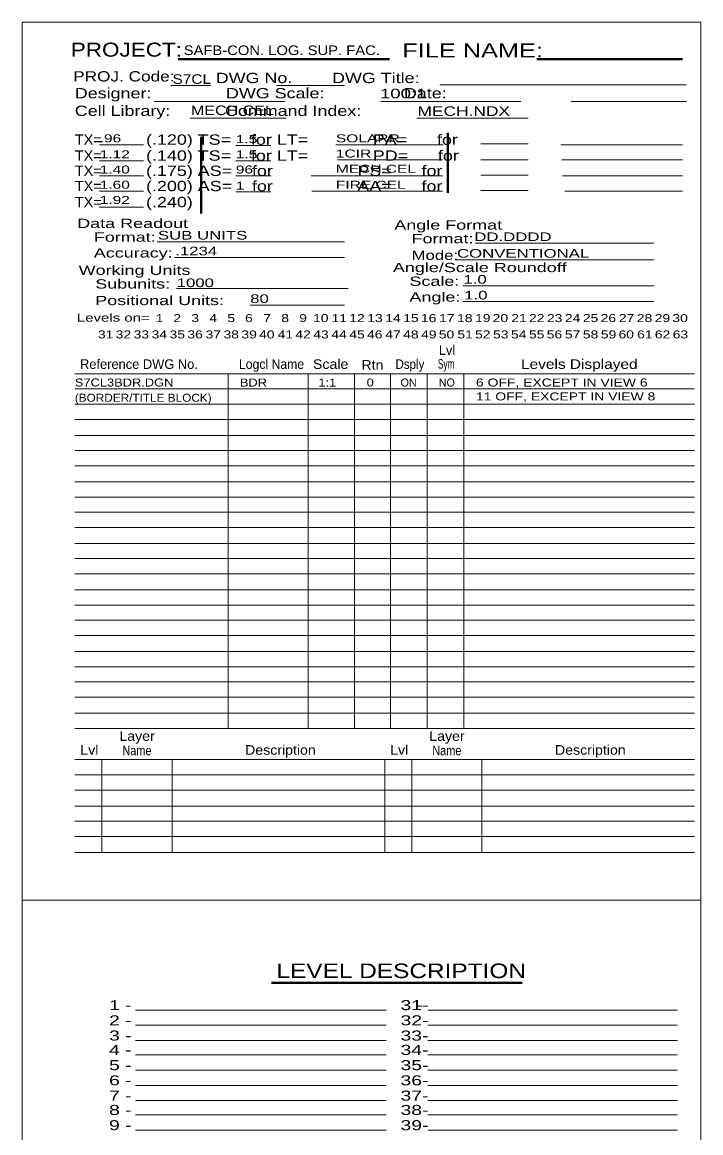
# Model space of a CAD drawing. Extents: x 55 to 190, y 198 to 264.
# Drawn here: x 168.12 to 189.71, y 221.76 to 257.1 of the extents above; entities that cross this region are included whole.
import ezdxf
from ezdxf.enums import TextEntityAlignment as Align

# ---------------------------------------------------------------- set-up
doc = ezdxf.new("R2010")
doc.units = 0
doc.header["$LTSCALE"] = 0.1
for name, color, linetype, lineweight in [('1', 7, 'Continuous', 25), ('2', 7, 'Continuous', 40), ('3', 7, 'Continuous', 25), ('5', 7, 'Continuous', 35), ('6', 7, 'Continuous', 25), ('8', 7, 'Continuous', 13)]:
    doc.layers.add(name, color=color, linetype=linetype, lineweight=lineweight)
for name, color, linetype in [('10', 7, 'Continuous'), ('11', 7, 'Continuous'), ('12', 7, 'Continuous'), ('13', 7, 'Continuous'), ('14', 7, 'Continuous'), ('15', 7, 'Continuous'), ('16', 7, 'Continuous'), ('17', 7, 'Continuous'), ('18', 7, 'Continuous'), ('19', 7, 'Continuous'), ('20', 7, 'Continuous'), ('21', 7, 'Continuous'), ('22', 7, 'Continuous'), ('23', 7, 'Continuous'), ('24', 7, 'Continuous'), ('25', 7, 'Continuous'), ('26', 7, 'Continuous'), ('27', 7, 'Continuous'), ('28', 7, 'Continuous'), ('29', 7, 'Continuous'), ('30', 7, 'Continuous'), ('31', 7, 'Continuous'), ('32', 7, 'Continuous'), ('33', 7, 'Continuous'), ('34', 7, 'Continuous'), ('35', 7, 'Continuous'), ('36', 7, 'Continuous'), ('37', 7, 'Continuous'), ('38', 7, 'Continuous'), ('39', 7, 'Continuous'), ('4', 7, 'Continuous'), ('40', 7, 'Continuous'), ('41', 7, 'Continuous'), ('42', 7, 'Continuous'), ('43', 7, 'Continuous'), ('44', 7, 'Continuous'), ('45', 7, 'Continuous'), ('46', 7, 'Continuous'), ('47', 7, 'Continuous'), ('48', 7, 'Continuous'), ('49', 7, 'Continuous'), ('50', 7, 'Continuous'), ('51', 7, 'Continuous'), ('52', 7, 'Continuous'), ('53', 7, 'Continuous'), ('54', 7, 'Continuous'), ('55', 7, 'Continuous'), ('56', 7, 'Continuous'), ('57', 7, 'Continuous'), ('58', 7, 'Continuous'), ('59', 7, 'Continuous'), ('60', 7, 'Continuous'), ('61', 7, 'Continuous'), ('62', 7, 'Continuous'), ('63', 7, 'Continuous'), ('7', 7, 'Continuous'), ('9', 7, 'Continuous')]:
    doc.layers.add(name, color=color, linetype=linetype)

msp = doc.modelspace()

# ---------------------------------------------------------------- linework, layer by layer
at = {"layer": '3', "lineweight": 13}
for points in [[(168.1177, 257.1025), (189.7077, 257.1025), (189.7077, 229.1625), (168.1177, 229.1625)], [(168.1177, 229.1625), (189.7077, 229.1625), (189.7077, 201.2225), (168.1177, 201.2225)]]:
    msp.add_lwpolyline(points, close=True, dxfattribs=at)
at = {"layer": '8', "lineweight": 40}
for p, q in [((179.804, 255.93), (173.0777, 255.93)), ((189.1277, 255.93), (184.4915, 255.93)), ((173.8165, 253.4587), (173.8165, 251.0137)), ((181.664, 251.675), (181.664, 253.5862)), ((176.0515, 226.5325), (184.0252, 226.5325))]:
    msp.add_line(p, q, dxfattribs=at)
at = {"layer": '8'}
for p, q in [((174.1227, 255.09), (172.8477, 255.09)), ((178.3765, 255.09), (176.2115, 255.09)), ((189.2565, 255.115), (181.409, 255.115)), ((172.3127, 254.5787), (176.4652, 254.5787)), ((179.5227, 254.5787), (183.9815, 254.5787)), ((185.5865, 254.5787), (189.2565, 254.5787)), ((173.4602, 254.045), (176.5177, 254.045)), ((180.6702, 254.045), (184.2115, 254.045)), ((171.9815, 253.2037), (170.5815, 253.2037)), ((176.0327, 253.1787), (174.9127, 253.1787)), ((181.5102, 253.2037), (178.0977, 253.2037)), ((184.2115, 253.2287), (182.7077, 253.2287)), ((189.1277, 253.2037), (185.2565, 253.2037)), ((171.9815, 252.695), (170.5815, 252.695)), ((176.0327, 252.695), (174.9127, 252.695)), ((181.4852, 252.72), (178.1477, 252.72)), ((184.2115, 252.72), (182.7077, 252.72)), ((189.1277, 252.72), (185.2815, 252.72)), ((171.9815, 252.2112), (170.5815, 252.2112)), ((176.0327, 252.2112), (174.9127, 252.2112)), ((181.4852, 252.2112), (177.3077, 252.2112)), ((184.2115, 252.2362), (182.7077, 252.2362)), ((189.1277, 252.2112), (185.3065, 252.2112)), ((171.9815, 251.7262), (170.5815, 251.7262)), ((176.0327, 251.7), (174.9127, 251.7)), ((181.4852, 251.7262), (177.3327, 251.7262)), ((184.2115, 251.7512), (182.7077, 251.7512)), ((189.1277, 251.7262), (185.3827, 251.7262)), ((171.9815, 251.2162), (170.5815, 251.2162)), ((178.3752, 250.1175), (172.4115, 250.1175)), ((182.524, 250.0687), (188.2115, 250.0687)), ((178.3752, 249.615), (172.9627, 249.615)), ((188.2115, 249.54), (181.9065, 249.54)), ((178.4902, 248.6275), (173.0315, 248.6275)), ((188.2115, 248.7137), (182.134, 248.7137)), ((178.3752, 248.1), (175.3715, 248.1)), ((188.2115, 248.2112), (182.134, 248.2112)), ((189.5102, 245.9175), (169.7915, 245.9175)), ((174.6752, 245.9175), (174.6752, 234.63)), ((177.219, 245.9175), (177.219, 234.63)), ((178.6865, 245.9175), (178.6865, 234.63)), ((179.834, 245.9175), (179.834, 234.6562)), ((181.004, 245.9175), (181.004, 234.63)), ((182.1727, 245.9175), (182.1727, 234.6562)), ((189.5102, 245.4325), (169.7915, 245.4325)), ((189.5102, 244.9487), (169.7915, 244.9487)), ((189.5102, 244.465), (169.7915, 244.465)), ((189.5102, 243.9562), (169.7915, 243.9562)), ((189.5102, 243.4725), (169.7915, 243.4725)), ((189.5102, 242.9875), (169.7915, 242.9875)), ((189.5102, 242.4775), (169.7915, 242.4775)), ((189.5102, 241.9937), (169.7915, 241.9937)), ((189.5102, 241.5087), (169.7915, 241.5087)), ((189.5102, 241.025), (169.7915, 241.025)), ((189.5102, 240.5162), (169.7915, 240.5162)), ((189.5102, 240.0325), (169.7915, 240.0325)), ((189.5102, 239.5487), (169.7915, 239.5487)), ((189.5102, 239.0375), (169.7915, 239.0375)), ((189.5102, 238.5537), (169.7915, 238.5537)), ((189.5102, 238.07), (169.7915, 238.07)), ((189.5102, 237.5862), (169.7915, 237.5862)), ((189.5102, 237.0762), (169.7915, 237.0762)), ((189.5102, 236.5925), (169.7915, 236.5925)), ((189.5102, 236.1087), (169.7915, 236.1087)), ((189.5102, 235.625), (169.7915, 235.625)), ((189.5102, 235.1137), (169.7915, 235.1137)), ((189.5102, 234.63), (169.7915, 234.63)), ((189.5102, 233.6375), (169.7915, 233.6375)), ((170.6552, 233.6375), (170.6552, 230.6812)), ((172.8865, 233.6375), (172.8865, 230.6812)), ((179.6515, 233.6375), (179.6515, 230.6812)), ((180.5152, 233.6375), (180.5152, 230.6812)), ((182.7465, 233.6375), (182.7465, 230.6812)), ((189.5102, 233.1525), (169.7915, 233.1525)), ((189.5102, 232.6687), (169.7915, 232.6687)), ((189.5102, 232.16), (169.7915, 232.16)), ((189.5102, 231.6762), (169.7915, 231.6762)), ((189.5102, 231.1925), (169.7915, 231.1925)), ((189.5102, 230.6812), (169.7915, 230.6812)), ((168.1177, 229.1625), (189.7077, 229.1625)), ((171.7202, 225.6662), (179.694, 225.6662)), ((181.019, 225.6662), (188.9677, 225.6662)), ((171.7202, 225.1825), (179.694, 225.1825)), ((181.019, 225.1825), (188.9677, 225.1825)), ((171.7202, 224.6975), (179.694, 224.6975)), ((181.019, 224.6975), (188.9677, 224.6975)), ((171.7202, 224.2412), (179.694, 224.2412)), ((181.019, 224.2412), (188.9677, 224.2412)), ((171.7202, 223.7562), (179.694, 223.7562)), ((181.019, 223.7562), (188.9677, 223.7562)), ((171.7202, 223.2725), (179.694, 223.2725)), ((181.019, 223.2725), (188.9677, 223.2725)), ((171.7202, 222.7862), (179.694, 222.7862)), ((181.019, 222.7862), (188.9677, 222.7862)), ((171.7202, 222.33), (179.694, 222.33)), ((181.019, 222.33), (188.9677, 222.33)), ((171.7202, 221.845), (179.694, 221.845)), ((181.019, 221.845), (188.9677, 221.845))]:
    msp.add_line(p, q, dxfattribs=at)

# ---------------------------------------------------------------- texts
at = {"layer": '1', "width": 1.3}
msp.add_text('1', height=0.2546, dxfattribs=at).set_placement((172.4875, 247.56), align=Align.CENTER)
at = {"layer": '10'}
for s, height, width, p in [('100:1         ', 0.3057, 1.45, (179.4977, 254.68)), ('.96 ', 0.2546, 1.45, (170.5815, 253.28)), ('1.5 ', 0.2546, 1.45, (174.9127, 253.255)), ('1.12', 0.2546, 1.45, (170.5815, 252.7712)), ('1.5 ', 0.2546, 1.45, (174.9127, 252.7712)), ('1.40', 0.2546, 1.45, (170.5815, 252.2875)), ('96  ', 0.2546, 1.45, (174.9127, 252.2875)), ('1.60', 0.2546, 1.45, (170.5815, 251.8037)), ('1   ', 0.2546, 1.45, (174.9127, 251.7762)), ('1.92', 0.2546, 1.45, (170.5815, 251.3187)), ('1000                ', 0.2751, 1.45, (173.0315, 248.6737)), ('80       ', 0.2751, 1.45, (175.3715, 248.1687)), ('Levels on=', 0.2546, 1.4, (169.8565, 247.5737))]:
    msp.add_text(s, height=height, dxfattribs=dict(at, width=width)).set_placement(p)
at = {"layer": '10', "width": 1.3}
msp.add_text('10', height=0.2546, dxfattribs=at).set_placement((177.616, 247.56), align=Align.CENTER)
at = {"layer": '11', "width": 1.3}
msp.add_text('11', height=0.2546, dxfattribs=at).set_placement((178.2072, 247.56), align=Align.CENTER)
at = {"layer": '12', "width": 1.3}
msp.add_text('12', height=0.2546, dxfattribs=at).set_placement((178.7697, 247.56), align=Align.CENTER)
at = {"layer": '13', "width": 1.3}
msp.add_text('13', height=0.2546, dxfattribs=at).set_placement((179.341, 247.56), align=Align.CENTER)
at = {"layer": '14', "width": 1.3}
msp.add_text('14', height=0.2546, dxfattribs=at).set_placement((179.9135, 247.56), align=Align.CENTER)
at = {"layer": '15', "width": 1.3}
msp.add_text('15', height=0.2546, dxfattribs=at).set_placement((180.4847, 247.56), align=Align.CENTER)
at = {"layer": '16', "width": 1.3}
msp.add_text('16', height=0.2546, dxfattribs=at).set_placement((181.0497, 247.56), align=Align.CENTER)
at = {"layer": '17', "width": 1.3}
msp.add_text('17', height=0.2546, dxfattribs=at).set_placement((181.6272, 247.56), align=Align.CENTER)
at = {"layer": '18', "width": 1.3}
msp.add_text('18', height=0.2546, dxfattribs=at).set_placement((182.1997, 247.56), align=Align.CENTER)
at = {"layer": '19', "width": 1.3}
msp.add_text('19', height=0.2546, dxfattribs=at).set_placement((182.771, 247.56), align=Align.CENTER)
at = {"layer": '2', "width": 1.3}
msp.add_text('2', height=0.2546, dxfattribs=at).set_placement((173.05, 247.56), align=Align.CENTER)
at = {"layer": '20', "width": 1.3}
msp.add_text('20', height=0.2546, dxfattribs=at).set_placement((183.3322, 247.56), align=Align.CENTER)
at = {"layer": '21', "width": 1.3}
msp.add_text('21', height=0.2546, dxfattribs=at).set_placement((183.9247, 247.56), align=Align.CENTER)
at = {"layer": '22', "width": 1.3}
msp.add_text('22', height=0.2546, dxfattribs=at).set_placement((184.4872, 247.56), align=Align.CENTER)
at = {"layer": '23', "width": 1.3}
msp.add_text('23', height=0.2546, dxfattribs=at).set_placement((185.0597, 247.56), align=Align.CENTER)
at = {"layer": '24', "width": 1.3}
msp.add_text('24', height=0.2546, dxfattribs=at).set_placement((185.631, 247.56), align=Align.CENTER)
at = {"layer": '25', "width": 1.3}
msp.add_text('25', height=0.2546, dxfattribs=at).set_placement((186.201, 247.56), align=Align.CENTER)
at = {"layer": '26', "width": 1.3}
msp.add_text('26', height=0.2546, dxfattribs=at).set_placement((186.7672, 247.56), align=Align.CENTER)
at = {"layer": '27', "width": 1.3}
msp.add_text('27', height=0.2546, dxfattribs=at).set_placement((187.346, 247.56), align=Align.CENTER)
at = {"layer": '28', "width": 1.3}
msp.add_text('28', height=0.2546, dxfattribs=at).set_placement((187.9172, 247.56), align=Align.CENTER)
at = {"layer": '29', "width": 1.3}
msp.add_text('29', height=0.2546, dxfattribs=at).set_placement((188.4872, 247.56), align=Align.CENTER)
at = {"layer": '3', "width": 1.3}
msp.add_text('3', height=0.2546, dxfattribs=at).set_placement((173.6225, 247.56), align=Align.CENTER)
at = {"layer": '30', "width": 1.3}
msp.add_text('30', height=0.2546, dxfattribs=at).set_placement((189.0497, 247.56), align=Align.CENTER)
at = {"layer": '31', "width": 1.3}
msp.add_text('31', height=0.2546, dxfattribs=at).set_placement((170.7722, 247.04), align=Align.CENTER)
at = {"layer": '32', "width": 1.3}
msp.add_text('32', height=0.2546, dxfattribs=at).set_placement((171.3372, 247.04), align=Align.CENTER)
at = {"layer": '33', "width": 1.3}
msp.add_text('33', height=0.2546, dxfattribs=at).set_placement((171.9085, 247.04), align=Align.CENTER)
at = {"layer": '34', "width": 1.3}
msp.add_text('34', height=0.2546, dxfattribs=at).set_placement((172.4797, 247.04), align=Align.CENTER)
at = {"layer": '35', "width": 1.3}
msp.add_text('35', height=0.2546, dxfattribs=at).set_placement((173.051, 247.04), align=Align.CENTER)
at = {"layer": '36', "width": 1.3}
msp.add_text('36', height=0.2546, dxfattribs=at).set_placement((173.6172, 247.04), align=Align.CENTER)
at = {"layer": '37', "width": 1.3}
msp.add_text('37', height=0.2546, dxfattribs=at).set_placement((174.1947, 247.04), align=Align.CENTER)
at = {"layer": '38', "width": 1.3}
msp.add_text('38', height=0.2546, dxfattribs=at).set_placement((174.7672, 247.04), align=Align.CENTER)
at = {"layer": '39', "width": 1.3}
msp.add_text('39', height=0.2546, dxfattribs=at).set_placement((175.3372, 247.04), align=Align.CENTER)
at = {"layer": '4', "width": 1.3}
msp.add_text('4', height=0.2546, dxfattribs=at).set_placement((174.1937, 247.56), align=Align.CENTER)
at = {"layer": '40', "width": 1.3}
msp.add_text('40', height=0.2546, dxfattribs=at).set_placement((175.8997, 247.04), align=Align.CENTER)
at = {"layer": '41', "width": 1.3}
msp.add_text('41', height=0.2546, dxfattribs=at).set_placement((176.491, 247.04), align=Align.CENTER)
at = {"layer": '42', "width": 1.3}
msp.add_text('42', height=0.2546, dxfattribs=at).set_placement((177.0535, 247.04), align=Align.CENTER)
at = {"layer": '43', "width": 1.3}
msp.add_text('43', height=0.2546, dxfattribs=at).set_placement((177.6247, 247.04), align=Align.CENTER)
at = {"layer": '44', "width": 1.3}
msp.add_text('44', height=0.2546, dxfattribs=at).set_placement((178.1972, 247.04), align=Align.CENTER)
at = {"layer": '45', "width": 1.3}
msp.add_text('45', height=0.2546, dxfattribs=at).set_placement((178.7697, 247.04), align=Align.CENTER)
at = {"layer": '46', "width": 1.3}
msp.add_text('46', height=0.2546, dxfattribs=at).set_placement((179.3335, 247.04), align=Align.CENTER)
at = {"layer": '47', "width": 1.3}
msp.add_text('47', height=0.2546, dxfattribs=at).set_placement((179.9135, 247.04), align=Align.CENTER)
at = {"layer": '48', "width": 1.3}
msp.add_text('48', height=0.2546, dxfattribs=at).set_placement((180.4847, 247.04), align=Align.CENTER)
at = {"layer": '49', "width": 1.3}
msp.add_text('49', height=0.2546, dxfattribs=at).set_placement((181.0547, 247.04), align=Align.CENTER)
at = {"layer": '5', "width": 1.3}
msp.add_text('5', height=0.2546, dxfattribs=at).set_placement((174.7662, 247.56), align=Align.CENTER)
at = {"layer": '50', "width": 1.3}
msp.add_text('50', height=0.2546, dxfattribs=at).set_placement((181.6172, 247.04), align=Align.CENTER)
at = {"layer": '51', "width": 1.3}
msp.add_text('51', height=0.2546, dxfattribs=at).set_placement((182.2085, 247.04), align=Align.CENTER)
at = {"layer": '52', "width": 1.3}
msp.add_text('52', height=0.2546, dxfattribs=at).set_placement((182.771, 247.04), align=Align.CENTER)
at = {"layer": '53', "width": 1.3}
msp.add_text('53', height=0.2546, dxfattribs=at).set_placement((183.3435, 247.04), align=Align.CENTER)
at = {"layer": '54', "width": 1.3}
msp.add_text('54', height=0.2546, dxfattribs=at).set_placement((183.9147, 247.04), align=Align.CENTER)
at = {"layer": '55', "width": 1.3}
msp.add_text('55', height=0.2546, dxfattribs=at).set_placement((184.4872, 247.04), align=Align.CENTER)
at = {"layer": '56', "width": 1.3}
msp.add_text('56', height=0.2546, dxfattribs=at).set_placement((185.0522, 247.04), align=Align.CENTER)
at = {"layer": '57', "width": 1.3}
msp.add_text('57', height=0.2546, dxfattribs=at).set_placement((185.631, 247.04), align=Align.CENTER)
at = {"layer": '58', "width": 1.3}
msp.add_text('58', height=0.2546, dxfattribs=at).set_placement((186.201, 247.04), align=Align.CENTER)
at = {"layer": '59', "width": 1.3}
msp.add_text('59', height=0.2546, dxfattribs=at).set_placement((186.7735, 247.04), align=Align.CENTER)
at = {"layer": '6', "width": 1.3}
msp.add_text('6', height=0.2546, dxfattribs=at).set_placement((175.33, 247.56), align=Align.CENTER)
at = {"layer": '60', "width": 1.3}
msp.add_text('60', height=0.2546, dxfattribs=at).set_placement((187.336, 247.04), align=Align.CENTER)
at = {"layer": '61', "width": 1.3}
msp.add_text('61', height=0.2546, dxfattribs=at).set_placement((187.9272, 247.04), align=Align.CENTER)
at = {"layer": '62', "width": 1.3}
msp.add_text('62', height=0.2546, dxfattribs=at).set_placement((188.4897, 247.04), align=Align.CENTER)
at = {"layer": '63', "width": 1.3}
msp.add_text('63', height=0.2546, dxfattribs=at).set_placement((189.061, 247.04), align=Align.CENTER)
at = {"layer": '7', "width": 1.3}
msp.add_text('7', height=0.2546, dxfattribs=at).set_placement((175.91, 247.56), align=Align.CENTER)
at = {"layer": '8'}
for s, height, width, p in [('PROJECT:', 0.4459, 1.2, (169.6627, 256.0062)), ('SAFB-CON. LOG. SUP. FAC.  ', 0.3057, 1.15, (173.2552, 256.0575)), ('FILE NAME:', 0.4459, 1.35, (180.2115, 255.9812)), ('PROJ. Code:', 0.3275, 1.25, (169.739, 255.2162)), ('DWG No.        DWG Title:', 0.3275, 1.3, (174.2752, 255.165)), ('S7CL', 0.3057, 1.2, (172.9002, 255.14)), ('Designer:               DWG Scale:                Date:', 0.3275, 1.3, (169.7915, 254.68)), ('Cell Library:           Command Index:', 0.3275, 1.3, (169.7915, 254.12)), ('MECH.CEL ', 0.3057, 1.25, (173.4852, 254.1462)), ('MECH.NDX   ', 0.3057, 1.35, (180.6952, 254.12)), ('TX=', 0.3275, 1.05, (169.7915, 253.2037)), ('(.120) TS=    for LT=             PA=      for', 0.3275, 1.3, (172.0577, 253.2037)), ('SOLARR      ', 0.2546, 1.45, (178.0977, 253.28)), ('(.140) TS=    for LT=             PD=      for', 0.3275, 1.3, (172.0577, 252.695)), ('1CIR        ', 0.2546, 1.45, (178.0977, 252.7962)), ('TX=', 0.3275, 1.05, (169.7915, 252.695)), ('TX=', 0.3275, 1.05, (169.7915, 252.2112)), ('(.175) AS=    for                 PS=      for', 0.3275, 1.3, (172.0577, 252.2112)), ('MECH.CEL    ', 0.2546, 1.45, (178.0977, 252.3125)), ('TX=', 0.3275, 1.05, (169.7915, 251.7262)), ('(.200) AS=    for                 AA=      for', 0.3275, 1.3, (172.0577, 251.7262)), ('FIRE.CEL    ', 0.2546, 1.45, (178.0977, 251.8037)), ('TX=', 0.3275, 1.05, (169.7915, 251.2162)), ('(.240)', 0.3275, 1.3, (172.0577, 251.2162)), ('Data Readout', 0.2948, 1.45, (169.8677, 250.5537)), ('Angle Format', 0.2948, 1.45, (179.9565, 250.5025)), ('Format:', 0.2948, 1.45, (170.3952, 250.1175)), ('Format:', 0.2948, 1.45, (180.5065, 250.0687)), ('DD.DDDD             ', 0.2751, 1.45, (182.5015, 250.1375)), ('Accuracy:', 0.2948, 1.45, (170.3952, 249.615)), ('CONVENTIONAL        ', 0.2751, 1.45, (181.9502, 249.6087)), ('Mode:', 0.2948, 1.35, (180.5065, 249.54)), ('Working Units', 0.2948, 1.45, (169.914, 249.0637)), ('Angle/Scale Roundoff', 0.2948, 1.45, (179.9115, 249.15)), ('Subunits:', 0.2948, 1.45, (170.4415, 248.6275)), ('Scale:', 0.2948, 1.45, (180.4377, 248.7137)), ('1.0                 ', 0.2751, 1.45, (182.1565, 248.7825)), ('Angle:', 0.2948, 1.45, (180.4377, 248.2112)), ('1.0                 ', 0.2751, 1.45, (182.1802, 248.28)), ('Positional Units:', 0.2948, 1.45, (170.4415, 248.1)), ('S7CL3BDR.DGN           ', 0.2548, 1.2, (169.7915, 245.51)), ('BDR       ', 0.2546, 1.2, (175.0427, 245.51)), (' 1:1 ', 0.2548, 1.2, (177.4265, 245.51)), ('6 OFF, EXCEPT IN VIEW 6       ', 0.2546, 1.3, (182.5552, 245.51)), ('(BORDER/TITLE BLOCK)   ', 0.2548, 1.1, (169.7915, 245.025)), ('11 OFF, EXCEPT IN VIEW 8      ', 0.2546, 1.3, (182.5552, 245.0675)), ('1 -', 0.3184, 1.45, (170.8802, 225.6662)), ('31-', 0.3184, 1.45, (180.1527, 225.6662)), ('3 -', 0.3184, 1.45, (180.1527, 225.6662)), ('2 -', 0.3184, 1.45, (170.8802, 225.1825)), ('32-', 0.3184, 1.45, (180.1527, 225.1825)), ('3 -', 0.3184, 1.45, (170.8802, 224.6975)), ('33-', 0.3184, 1.45, (180.1527, 224.6975)), ('4 -', 0.3184, 1.45, (170.8802, 224.2412)), ('34-', 0.3184, 1.45, (180.1527, 224.2412)), ('5 -', 0.3184, 1.45, (170.8802, 223.7562)), ('35-', 0.3184, 1.45, (180.1527, 223.7562)), ('6 -', 0.3184, 1.45, (170.8802, 223.2725)), ('36-', 0.3184, 1.45, (180.1527, 223.2725)), ('7 -', 0.3184, 1.45, (170.8802, 222.7862)), ('37-', 0.3184, 1.45, (180.1527, 222.7862)), ('8 -', 0.3184, 1.45, (170.8802, 222.33)), ('38-', 0.3184, 1.45, (180.1527, 222.33)), ('9 -', 0.3184, 1.45, (170.8802, 221.845)), ('39-', 0.3184, 1.45, (180.1527, 221.845))]:
    msp.add_text(s, height=height, dxfattribs=dict(at, width=width)).set_placement(p)
for s, height, width, p in [('8', 0.2546, 1.3, (176.4825, 247.56)), ('Logcl Name', 0.3057, 0.95, (176.0506, 246.07)), ('Scale', 0.3057, 1.1, (177.931, 246.07)), ('Rtn', 0.3057, 1.1, (179.2604, 246.045)), ('Dsply', 0.3057, 0.9, (180.4536, 246.07)), ('Sym', 0.3057, 0.65, (181.6078, 246.0775)), ('Levels Displayed', 0.3057, 1.2, (185.8422, 246.07)), ('Layer', 0.3057, 1.1, (171.7722, 234.2337)), ('Layer', 0.3057, 1.1, (181.6322, 234.2337)), ('Lvl', 0.3057, 1.1, (170.2542, 233.7925)), ('Name', 0.3057, 0.85, (171.7688, 233.775)), ('Description', 0.3057, 1.1, (176.3339, 233.7925)), ('Lvl', 0.3057, 1.1, (180.1129, 233.7925)), ('Name', 0.3057, 0.85, (181.6288, 233.775)), ('Description', 0.3057, 1.1, (186.1939, 233.7925)), ('LEVEL DESCRIPTION', 0.4644, 1.25, (180.1761, 226.685))]:
    msp.add_text(s, height=height, dxfattribs=dict(at, width=width)).set_placement(p, align=Align.CENTER)
for s, p in [('Lvl', (181.6328, 246.5162)), ('Reference DWG No.', (171.8318, 246.07))]:
    msp.add_text(s, height=0.3057, dxfattribs=at).set_placement(p, align=Align.CENTER)
for s, p in [('ON ', (180.1565, 245.51)), ('NO ', (181.3727, 245.51))]:
    msp.add_text(s, height=0.2546, dxfattribs=at).set_placement(p)
at = {"layer": '9'}
for s, height, width, p in [('SUB UNITS           ', 0.2751, 1.45, (172.4352, 250.1862)), ('.1234               ', 0.2751, 1.45, (172.9865, 249.6837)), (' 0 ', 0.2546, 1.2, (178.9627, 245.51))]:
    msp.add_text(s, height=height, dxfattribs=dict(at, width=width)).set_placement(p)
at = {"layer": '9', "width": 1.3}
msp.add_text('9', height=0.2546, dxfattribs=at).set_placement((177.0525, 247.56), align=Align.CENTER)

doc.saveas('drawing.dxf')
